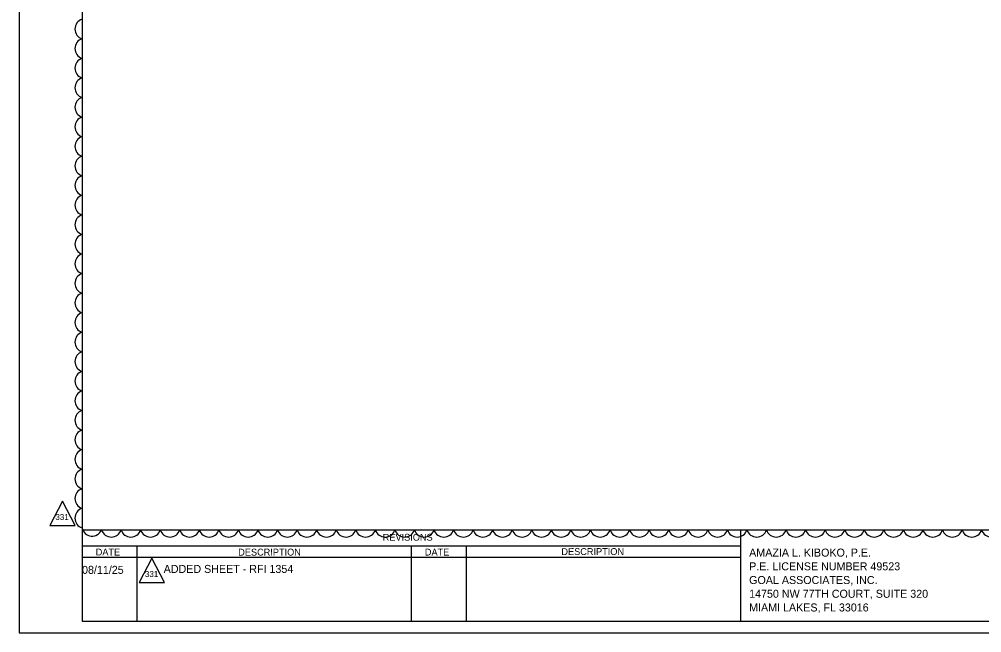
# Model space of a CAD drawing. Extents: x -816.9 to -790.1, y -2199.5 to -2188.9.
# Drawn here: x -811.34 to -802.91, y -2199.5 to -2194.13 of the extents above; entities that cross this region are included whole.
import ezdxf

# ---------------------------------------------------------------- set-up
doc = ezdxf.new("R2010")
doc.units = 0
for name, color, linetype in [('AdhocPoint_dp', 7, 'Continuous'), ('Cloud_dp', 7, 'Continuous'), ('PlotBorder_dp', 7, 'Continuous'), ('SheetBorder_dp', 7, 'Continuous'), ('SheetLines_dp', 7, 'Continuous'), ('TextLabel', 7, 'Continuous'), ('TextMisc', 7, 'Continuous'), ('TextTitle', 7, 'Continuous')]:
    doc.layers.add(name, color=color, linetype=linetype)

msp = doc.modelspace()

# ---------------------------------------------------------------- linework, layer by layer
at = {"layer": 'AdhocPoint_dp'}
msp.add_line((-811.3358, -2199.5006), (-811.3358, -2199.5006), dxfattribs=at)
at = {"layer": 'Cloud_dp'}
for points in [[(-810.9581, -2198.3492), (-811.069, -2198.5629), (-810.8472, -2198.5629)], [(-810.1749, -2198.8478), (-810.2858, -2199.0614), (-810.064, -2199.0614)]]:
    msp.add_lwpolyline(points, close=True, dxfattribs=at)
for centre, radius, start, end in [((-810.7588, -2194.2199), 0.0897, 107.5, 252.5), ((-810.7588, -2194.391), 0.0897, 107.5, 252.5), ((-810.7588, -2194.5621), 0.0897, 107.5, 252.5), ((-810.7588, -2194.7332), 0.0897, 107.5, 252.5), ((-810.7588, -2194.9044), 0.0897, 107.5, 252.5), ((-810.7588, -2195.0755), 0.0897, 107.5, 252.5), ((-810.7588, -2195.2466), 0.0897, 107.5, 252.5), ((-810.7588, -2195.4177), 0.0897, 107.5, 252.5), ((-810.7588, -2195.5889), 0.0897, 107.5, 252.5), ((-810.7588, -2195.76), 0.0897, 107.5, 252.5), ((-810.7588, -2195.9311), 0.0897, 107.5, 252.5), ((-810.7588, -2196.1022), 0.0897, 107.5, 252.5), ((-810.7588, -2196.2733), 0.0897, 107.5, 252.5), ((-810.7588, -2196.4445), 0.0897, 107.5, 252.5), ((-810.7588, -2196.6156), 0.0897, 107.5, 252.5), ((-810.7588, -2196.7867), 0.0897, 107.5, 252.5), ((-810.7588, -2196.9578), 0.0897, 107.5, 252.5), ((-810.7588, -2197.129), 0.0897, 107.5, 252.5), ((-810.7588, -2197.3001), 0.0897, 107.5, 252.5), ((-810.7588, -2197.4712), 0.0897, 107.5, 252.5), ((-810.7588, -2197.6423), 0.0897, 107.5, 252.5), ((-810.7588, -2197.8134), 0.0897, 107.5, 252.5), ((-810.7588, -2197.9846), 0.0897, 107.5, 252.5), ((-810.7588, -2198.1557), 0.0897, 107.5, 252.5), ((-810.7588, -2198.3268), 0.0897, 107.5, 252.5), ((-810.7588, -2198.4979), 0.0897, 107.5, 252.5), ((-810.698, -2198.5653), 0.0896, 191.74536, 336.74536), ((-810.5301, -2198.5737), 0.0897, 197.5, 342.5), ((-810.359, -2198.5737), 0.0897, 197.5, 342.5), ((-810.1879, -2198.5737), 0.0897, 197.5, 342.5), ((-810.0167, -2198.5737), 0.0897, 197.5, 342.5), ((-809.8456, -2198.5737), 0.0897, 197.5, 342.5), ((-809.6745, -2198.5737), 0.0897, 197.5, 342.5), ((-809.5034, -2198.5737), 0.0897, 197.5, 342.5), ((-809.3323, -2198.5737), 0.0897, 197.5, 342.5), ((-809.1611, -2198.5737), 0.0897, 197.5, 342.5), ((-808.99, -2198.5737), 0.0897, 197.5, 342.5), ((-808.8189, -2198.5737), 0.0897, 197.5, 342.5), ((-808.6478, -2198.5737), 0.0897, 197.5, 342.5), ((-808.4766, -2198.5737), 0.0897, 197.5, 342.5), ((-808.3055, -2198.5737), 0.0897, 197.5, 342.5), ((-808.1344, -2198.5737), 0.0897, 197.5, 342.5), ((-807.9633, -2198.5737), 0.0897, 197.5, 342.5), ((-807.7921, -2198.5737), 0.0897, 197.5, 342.5), ((-807.621, -2198.5737), 0.0897, 197.5, 342.5), ((-807.4499, -2198.5737), 0.0897, 197.5, 342.5), ((-807.2788, -2198.5737), 0.0897, 197.5, 342.5), ((-807.1077, -2198.5737), 0.0897, 197.5, 342.5), ((-806.9365, -2198.5737), 0.0897, 197.5, 342.5), ((-806.7654, -2198.5737), 0.0897, 197.5, 342.5), ((-806.5943, -2198.5737), 0.0897, 197.5, 342.5), ((-806.4232, -2198.5737), 0.0897, 197.5, 342.5), ((-806.252, -2198.5737), 0.0897, 197.5, 342.5), ((-806.0809, -2198.5737), 0.0897, 197.5, 342.5), ((-805.9098, -2198.5737), 0.0897, 197.5, 342.5), ((-805.7387, -2198.5737), 0.0897, 197.5, 342.5), ((-805.5676, -2198.5737), 0.0897, 197.5, 342.5), ((-805.3964, -2198.5737), 0.0897, 197.5, 342.5), ((-805.2253, -2198.5737), 0.0897, 197.5, 342.5), ((-805.0542, -2198.5737), 0.0897, 197.5, 342.5), ((-804.8831, -2198.5737), 0.0897, 197.5, 342.5), ((-804.7119, -2198.5737), 0.0897, 197.5, 342.5), ((-804.5408, -2198.5737), 0.0897, 197.5, 342.5), ((-804.3697, -2198.5737), 0.0897, 197.5, 342.5), ((-804.1986, -2198.5737), 0.0897, 197.5, 342.5), ((-804.0275, -2198.5737), 0.0897, 197.5, 342.5), ((-803.8563, -2198.5737), 0.0897, 197.5, 342.5), ((-803.6852, -2198.5737), 0.0897, 197.5, 342.5), ((-803.5141, -2198.5737), 0.0897, 197.5, 342.5), ((-803.343, -2198.5737), 0.0897, 197.5, 342.5), ((-803.1718, -2198.5737), 0.0897, 197.5, 342.5), ((-803.0007, -2198.5737), 0.0897, 197.5, 342.5), ((-802.8296, -2198.5737), 0.0897, 197.5, 342.5)]:
    msp.add_arc(centre, radius, start, end, dxfattribs=at)
at = {"layer": 'PlotBorder_dp'}
msp.add_lwpolyline([(-811.3358, -2199.5006), (-794.8358, -2199.5006), (-794.8358, -2188.9006), (-811.3358, -2188.9006)], close=True, dxfattribs=at)
at = {"layer": 'SheetBorder_dp'}
for p, q in [((-810.7858, -2189.0006), (-810.7858, -2199.4006)), ((-810.7858, -2198.6006), (-795.3858, -2198.6006)), ((-810.7858, -2199.4006), (-795.3858, -2199.4006))]:
    msp.add_line(p, q, dxfattribs=at)
at = {"layer": 'SheetLines_dp'}
for p, q in [((-805.0258, -2198.6006), (-805.0258, -2199.4006)), ((-810.7858, -2198.7406), (-805.0258, -2198.7406)), ((-810.3058, -2198.7406), (-810.3058, -2199.4006)), ((-807.9058, -2198.7406), (-807.9058, -2199.4006)), ((-807.4258, -2198.7406), (-807.4258, -2199.4006)), ((-810.7858, -2198.8406), (-805.0258, -2198.8406))]:
    msp.add_line(p, q, dxfattribs=at)

# ---------------------------------------------------------------- texts
at = {"layer": 'Cloud_dp'}
for p in [(-811.0197, -2198.5147), (-810.2365, -2199.0133)]:
    msp.add_text('331', height=0.0525, rotation=360, dxfattribs=at).set_placement(p)
at = {"layer": 'TextLabel'}
for s, p in [('08/11/25', (-810.7864, -2198.9855)), ('ADDED SHEET - RFI 1354', (-810.0721, -2198.9774))]:
    msp.add_text(s, height=0.07, rotation=0, dxfattribs=at).set_placement(p)
at = {"layer": 'TextMisc'}
msp.add_text('REVISIONS', height=0.06, dxfattribs=at).set_placement((-808.1553, -2198.6955))
for s, rotation, p in [('DATE', 359.86925, (-810.6668, -2198.8247)), ('DESCRIPTION', 0.04975, (-809.4198, -2198.8259)), ('DATE', 359.86925, (-807.7868, -2198.8253)), ('DESCRIPTION', 0.04975, (-806.5922, -2198.8209))]:
    msp.add_text(s, height=0.06, rotation=rotation, dxfattribs=at).set_placement(p)
at = {"layer": 'TextTitle'}
for s, p in [('AMAZIA L. KIBOKO, P.E.', (-804.9493, -2198.8346)), ('P.E. LICENSE NUMBER 49523', (-804.9493, -2198.9546)), ('GOAL ASSOCIATES, INC.', (-804.9493, -2199.0746)), ('14750 NW 77TH COURT, SUITE 320', (-804.9493, -2199.1946)), ('MIAMI LAKES, FL 33016', (-804.9493, -2199.3146))]:
    msp.add_text(s, height=0.07, dxfattribs=at).set_placement(p)

doc.saveas('drawing.dxf')
